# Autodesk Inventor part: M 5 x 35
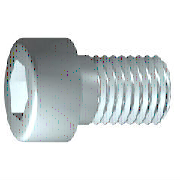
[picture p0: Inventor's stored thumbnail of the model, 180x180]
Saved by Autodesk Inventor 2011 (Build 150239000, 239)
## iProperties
IsCustomPart: 0
Company: 한국ATC센터
Created: 2014-12
Part Number: M 5 x 35
Material: 강, 연강
Description: 6각머리 태핑 나사
Document SubType Name: Modeling
Standard: KS B 1003
Designer: KYOUNG IL JANG
Standards Organization: KS
Language: ko-KR
Size Designation: M 5 x 35
Categories: <MemberInstance><Categories><Category DisplayName="조임쇠" InternalName="e4da775c-781d-43d5-af7c-5136215cf5a6" Mnemonic="FSTN"><Category DisplayName="볼트" InternalN
Density: 7.86 g/cm^3
Mass: 7.27786 g
Surface Area: 8.23857 cm^2
Volume: 0.925936 cm^3
Author: KYOUNG IL JANG
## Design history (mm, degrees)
body "Solid1"
workplane "Work Plane1"
fillet "Fillet2" dims "d30" = 0.1 (= R)
revolve "본체" stored, may be unused: angle "d10" = 90 deg
sketch "스케치2"
  geometry: L1 (0, -5.95)-(0, 5.95) reference; L2 (-5.95, 0)-(5.95, 0) reference; L3 (2.309, 0)-(1.155, -2); L4 (1.155, -2)-(-1.155, -2); L5 (-1.155, -2)-(-2.309, 0); L6 (-2.309, 0)-(-1.155, 2); L7 (-1.155, 2)-(1.155, 2); L8 (1.155, 2)-(2.309, 0); 2 further points
  constraints: 12 end point, 1 coincident, 1 horizontal alignment, 1 point on line, 12 other
extrude "슬롯" join sketch "스케치2" stored distance "d11" = 10; taper "d12" = 0 deg
fillet "모깎기1" dims "d17" = 0.5 (= RR)
feature "스레드" dims "d13" = 22 (= GEL), "d14" = 0
chamfer "모따기1" distance "d15" = 0.49076 (= -0.5 x SPD + 0.5 x GD); stored, may be unused: second distance "d16" = 0.49076 (= GUL), angle "d27" = 45 deg
sketch "스케치1"
  geometry: L1 (-1.167, 0)-(35, 0); L2 (35, 0)-(35, 2.5); L3 (35, 2.5)-(13, 2.5); L4 (13, 2.5)-(12.509, 2.5); L5 (12.509, 2.5)-(0, 2.5); L6 (0, 2.5)-(0, 4.25); L7 (0, 4.25)-(-5, 4.25); L8 (-5, 4.25)-(-5, 2.309); L9 (-5, 2.309)-(-2.5, 2.309); L10 (-2.5, 2.309)-(-1.167, 0); L11 (-13, 0)-(43, 0) reference; L12 (0, -0.85)-(0, 5.1) reference; L13 (13, 2.5)-(0, 2.5)
  constraints: 22 end point, 6 parallel, 2 collinear, 2 perpendicular, 1 horizontal, 1 point on line
  dimensions: "d1" = 22 distance from line of L3.end L2 (= GEL); "d2" = 0.49086 distance of L4.end L3.end (computed from GAL); "d3" = 5 distance between parallel lines of L8 L6 (= KOH); "d4" = 2.5 distance of L8.end L9.end (= INTI); "d5" = 60 deg angle of L10 L1; "d6" = 5 diameter of L3 L1 (= GD); "d7" = 5 diameter of L5 L1 (= BDM); "d8" = 4.6188 diameter of L9 L1 (= 1.1547 x SW); "d9" = 8.5 diameter of L7 L1 (= KOD); "d26" = 35 distance between parallel lines of L12 L2 (= NLG)
other parameters: "GD" = 5 (= NND) [user parameter; used in 2 equation terms], "NLG" = 35 [user parameter; used in 1 equation term], "GEL" = 22 [user parameter; used in 2 equation terms], "KOD" = 8.5 [user parameter; used in 1 equation term], "KOH" = 5 [user parameter; used in 1 equation term], "INTI" = 2.5 [user parameter; used in 1 equation term], "GAL" = 0.49076 (= 0.61345 x PTC) [user parameter; used in 1 equation term], "GUL" = 0.49076 (= 0.61345 x PTC) [user parameter; used in 1 equation term], "BDM" = 5 (= NND) [user parameter; used in 1 equation term], "SW" = 4 [user parameter; used in 2 equation terms], "RR" = 0.5 [user parameter; used in 1 equation term], "SPD" = 4.01848 (= NND - 1.2269 x PTC) [user parameter; used in 1 equation term], "d19" = 0, "d28" = 0, "d29" = 0, "R" = 0.1 [user parameter; used in 1 equation term], "PHH" = 0.2 [user parameter], "GD1" = 4.01848 (= THREADDIA - 1.2269 x PTC) [user parameter], "THREADDIA" = 5 [user parameter; used in 1 equation term], "FAWI" = 45 deg [user parameter], "TPU" = 12.5 (computed from PTC) [user parameter], "PTC" = 0.8 [user parameter; used in 5 equation terms], "NND" = 5 [user parameter; used in 3 equation terms], "TOA" = 30 deg [user parameter], "E0" = 4.62 (= 1.155 x SW) [user parameter]
